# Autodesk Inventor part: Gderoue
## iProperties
Author: patrick
Shininess: 20.0
Angle Display Precision: 2
Document Length Units: 11269
Document Angle Units: 11283
Document Time Units: 11279
Document Mass Units: 11290
Document Length Units Precision: 3
Document Angle Units Precision: 2
Compacted: True
PropertySet Name: _Private Model Information
Created: 2002-10
Part Number: Gderoue
Material: Par défaut
Document SubType Name: Modélisation
Designer: patrick
Control State: 0
Master: False
Checked Out: False
PropertySet Name: Design Tracking Control
Density: 0.0
Volumn: 0.0
Area: 0.0
PropertySet Name: Model Information
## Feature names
1. Révolution1 [Revolution]
